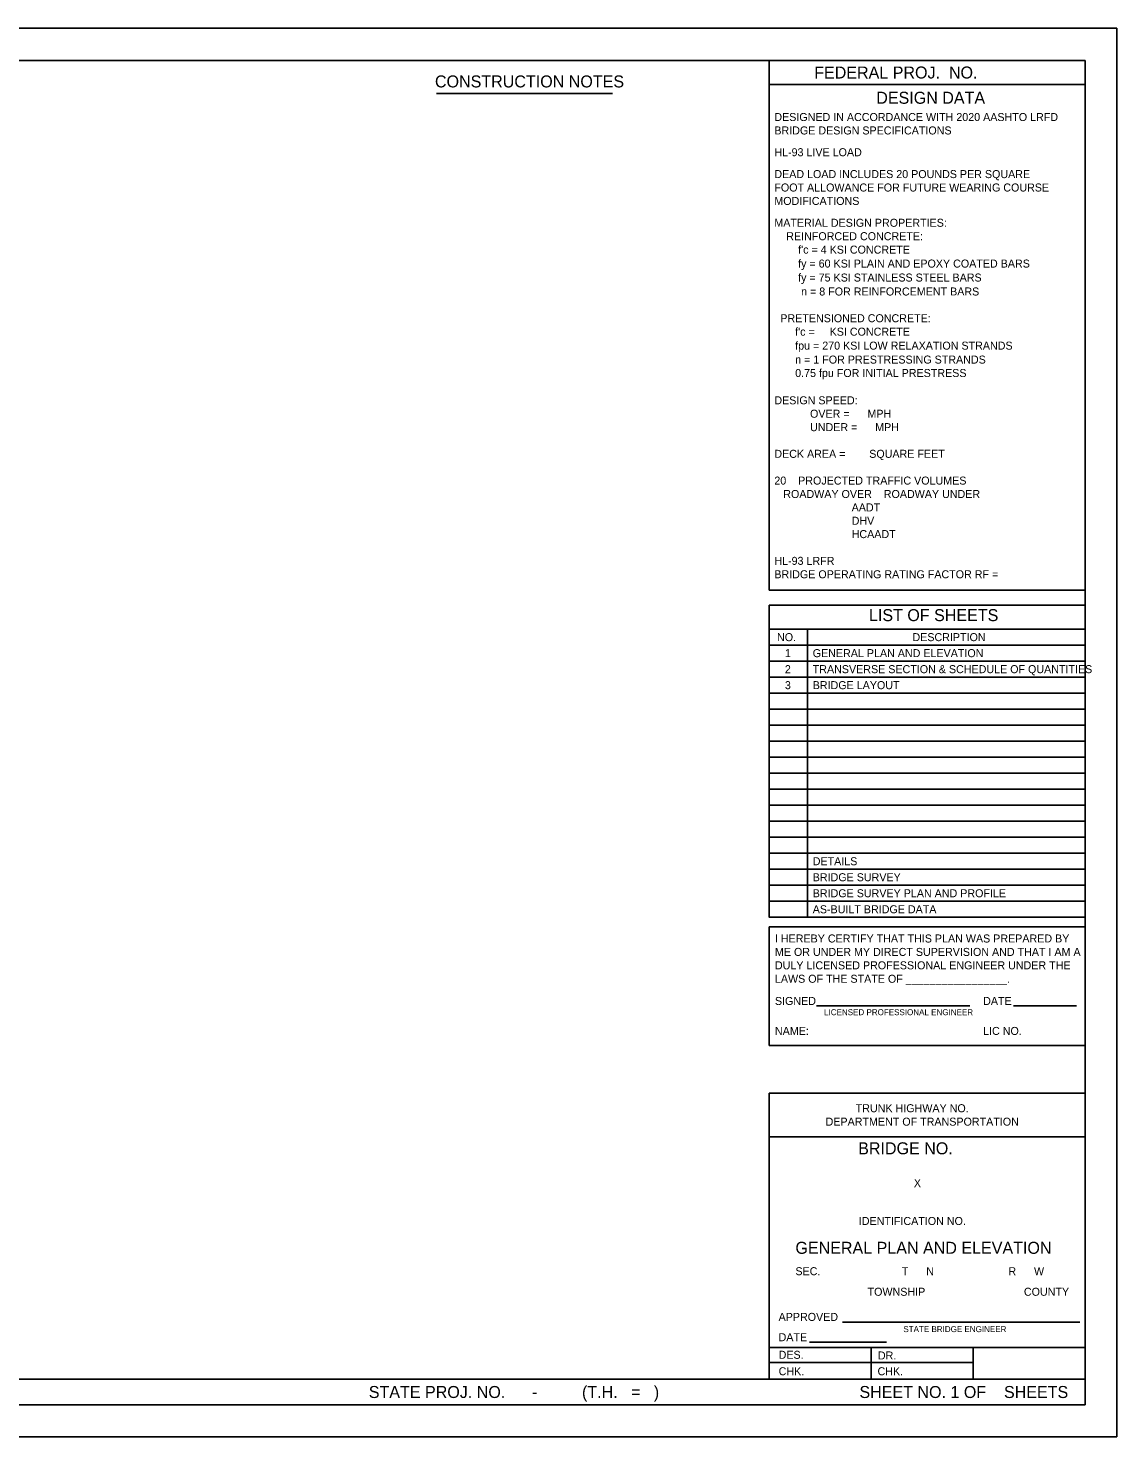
# Model space of a CAD drawing. Extents: x 0 to 1.42, y 0 to 0.92.
# Drawn here: x 0.708 to 1.417, y 0 to 0.917 of the extents above; entities that cross this region are included whole.
import ezdxf

# ---------------------------------------------------------------- set-up
doc = ezdxf.new("R2010")
doc.units = 0
for name, color, linetype in [('Border', 7, 'Continuous'), ('BR', 7, 'Continuous'), ('PLOT AIDS', 7, 'Continuous'), ('SHT1', 7, 'Continuous'), ('STD', 7, 'Continuous'), ('Txt', 7, 'Continuous')]:
    doc.layers.add(name, color=color, linetype=linetype)

msp = doc.modelspace()

# ---------------------------------------------------------------- linework, layer by layer
at = {"layer": 'Border'}
msp.add_lwpolyline([(0.0625, 0.89564), (1.39604, 0.89564), (1.39604, 0.02083), (0.0625, 0.02083)], close=True, dxfattribs=at)
at = {"layer": 'BR'}
for p, q in [((1.19052, 0.5256), (1.39604, 0.5256)), ((1.39604, 0.22365), (1.19052, 0.22365)), ((1.19052, 0.22365), (1.19052, 0.0375)), ((1.39604, 0.19526), (1.19052, 0.19526)), ((1.19052, 0.05819), (1.3961, 0.05819)), ((1.25687, 0.05819), (1.25687, 0.0375)), ((1.32317, 0.05819), (1.32317, 0.0375))]:
    msp.add_line(p, q, dxfattribs=at)
at = {"layer": 'PLOT AIDS'}
msp.add_lwpolyline([(0, 0.91668), (1.4167, 0.91668), (1.4167, 0), (0, 0)], close=True, dxfattribs=at)
at = {"layer": 'SHT1'}
for p, q in [((1.21536, 0.5256), (1.21536, 0.3381)), ((1.19052, 0.51518), (1.39604, 0.51518)), ((1.19052, 0.50477), (1.39604, 0.50477)), ((1.19052, 0.49435), (1.39604, 0.49435)), ((1.19052, 0.48393), (1.39604, 0.48393)), ((1.19052, 0.47352), (1.39604, 0.47352)), ((1.19052, 0.4631), (1.39604, 0.4631)), ((1.19052, 0.45268), (1.39604, 0.45268)), ((1.19052, 0.44227), (1.39604, 0.44227)), ((1.19052, 0.43185), (1.39604, 0.43185)), ((1.19052, 0.42143), (1.39604, 0.42143)), ((1.19052, 0.41102), (1.39604, 0.41102)), ((1.19052, 0.4006), (1.39604, 0.4006)), ((1.19052, 0.39018), (1.39604, 0.39018)), ((1.19052, 0.37977), (1.39604, 0.37977)), ((1.19052, 0.36935), (1.39604, 0.36935)), ((1.19052, 0.35893), (1.39604, 0.35893)), ((1.19052, 0.34852), (1.39604, 0.34852)), ((1.19052, 0.25468), (1.19052, 0.33187)), ((1.19052, 0.33187), (1.39604, 0.33187)), ((1.39604, 0.25468), (1.19052, 0.25468)), ((1.23821, 0.07469), (1.39258, 0.07469)), ((1.19052, 0.04838), (1.32317, 0.04838)), ((0.06258, 0.0375), (1.39596, 0.0375))]:
    msp.add_line(p, q, dxfattribs=at)
at = {"layer": 'STD'}
msp.add_lwpolyline([(1.19052, 0.5412), (1.39604, 0.5412), (1.39604, 0.3381), (1.19052, 0.3381)], close=True, dxfattribs=at)
at = {"layer": 'Txt'}
for p, q in [((1.19052, 0.89564), (1.19052, 0.55091)), ((1.19052, 0.88001), (1.39604, 0.88001)), ((0.97399, 0.87406), (1.08862, 0.87406)), ((1.19052, 0.55091), (1.39604, 0.55091)), ((1.2213, 0.28051), (1.32115, 0.28051)), ((1.34948, 0.28051), (1.39046, 0.28051)), ((1.21667, 0.06155), (1.26683, 0.06155))]:
    msp.add_line(p, q, dxfattribs=at)

# ---------------------------------------------------------------- texts
for s, height, p in [('FEDERAL PROJ.  NO.                 ', 0.0078125, (1.21979, 0.88392)), ('CONSTRUCTION NOTES', 0.0078125, (0.97304, 0.87811)), ('DESIGN DATA', 0.0078125, (1.26017, 0.86749)), ('DESIGNED IN ACCORDANCE WITH 2020 AASHTO LRFD', 0.0052083, (1.19386, 0.85625)), ('BRIDGE DESIGN SPECIFICATIONS', 0.0052083, (1.19386, 0.84752)), ('HL-93 LIVE LOAD', 0.0052083, (1.19386, 0.83334)), ('DEAD LOAD INCLUDES 20 POUNDS PER SQUARE', 0.0052083, (1.19386, 0.81912)), ('FOOT ALLOWANCE FOR FUTURE WEARING COURSE', 0.0052083, (1.19386, 0.81039)), ('MODIFICATIONS', 0.0052083, (1.19386, 0.80165)), ('MATERIAL DESIGN PROPERTIES:', 0.0052083, (1.19386, 0.78744)), ('    REINFORCED CONCRETE:', 0.0052083, (1.19386, 0.7787)), ("        f'c = 4 KSI CONCRETE", 0.0052083, (1.19386, 0.76997)), ('        fy = 60 KSI PLAIN AND EPOXY COATED BARS', 0.0052083, (1.19386, 0.76089)), ('        fy = 75 KSI STAINLESS STEEL BARS', 0.0052083, (1.19386, 0.7518)), ('         n = 8 FOR REINFORCEMENT BARS', 0.0052083, (1.19386, 0.74272)), ('  PRETENSIONED CONCRETE:', 0.0052083, (1.19386, 0.72531)), ("       f'c =     KSI CONCRETE", 0.0052083, (1.19386, 0.71657)), ('       fpu = 270 KSI LOW RELAXATION STRANDS', 0.0052083, (1.19386, 0.70749)), ('       n = 1 FOR PRESTRESSING STRANDS', 0.0052083, (1.19386, 0.69841)), ('       0.75 fpu FOR INITIAL PRESTRESS', 0.0052083, (1.19386, 0.68968)), ('DESIGN SPEED:', 0.0052083, (1.19386, 0.67191)), ('            OVER =      MPH', 0.0052083, (1.19386, 0.66318)), ('            UNDER =      MPH', 0.0052083, (1.19386, 0.65444)), ('DECK AREA =        SQUARE FEET', 0.0052083, (1.19386, 0.63708)), ('20    PROJECTED TRAFFIC VOLUMES', 0.0052083, (1.19386, 0.61967)), ('   ROADWAY OVER    ROADWAY UNDER', 0.0052083, (1.19386, 0.61093)), ('                          AADT         ', 0.0052083, (1.19386, 0.6022)), ('                          DHV          ', 0.0052083, (1.19386, 0.59352)), ('                          HCAADT       ', 0.0052083, (1.19386, 0.58484)), ('HL-93 LRFR', 0.005208, (1.19386, 0.56744)), ('BRIDGE OPERATING RATING FACTOR RF =    ', 0.0052083, (1.19386, 0.5587)), ('LIST OF SHEETS', 0.0078125, (1.25543, 0.53081)), ('NO.', 0.005208, (1.19562, 0.51779)), ('DESCRIPTION', 0.0052083, (1.28372, 0.51779)), ('1', 0.00521, (1.20071, 0.50737)), ('GENERAL PLAN AND ELEVATION', 0.0052083, (1.21883, 0.50737)), ('2', 0.00521, (1.20072, 0.49695)), ('TRANSVERSE SECTION & SCHEDULE OF QUANTITIES', 0.0052083, (1.21883, 0.49695)), ('3', 0.00521, (1.20074, 0.48654)), ('BRIDGE LAYOUT', 0.0052083, (1.21883, 0.48654)), ('DETAILS ', 0.005208, (1.21883, 0.37195)), ('BRIDGE SURVEY', 0.0052083, (1.21883, 0.36154)), ('BRIDGE SURVEY PLAN AND PROFILE', 0.0052083, (1.21883, 0.35112)), ('AS-BUILT BRIDGE DATA', 0.0052083, (1.21883, 0.3407)), ('I HEREBY CERTIFY THAT THIS PLAN WAS PREPARED BY', 0.0052083, (1.19424, 0.32169)), ('ME OR UNDER MY DIRECT SUPERVISION AND THAT I AM A', 0.0052083, (1.19424, 0.31295)), ('DULY LICENSED PROFESSIONAL ENGINEER UNDER THE', 0.0052083, (1.19424, 0.30422)), ('LAWS OF THE STATE OF _________________.', 0.0052083, (1.19424, 0.29548)), ('SIGNED', 0.005208, (1.19424, 0.28104)), ('DATE', 0.005208, (1.32971, 0.28104)), ('LICENSED PROFESSIONAL ENGINEER', 0.0039062, (1.22622, 0.27438)), ('NAME:                                         ', 0.0052083, (1.19424, 0.26153)), ('LIC NO.        ', 0.0052083, (1.32971, 0.26153)), ('TRUNK HIGHWAY NO.    ', 0.0052083, (1.2468, 0.21122)), ('DEPARTMENT OF TRANSPORTATION', 0.0052083, (1.2272, 0.20249)), ('BRIDGE NO.      ', 0.0078125, (1.24842, 0.18384)), ('X', 0.00521, (1.28464, 0.16246)), ('IDENTIFICATION NO.    ', 0.0052083, (1.24883, 0.13786)), ('GENERAL PLAN AND ELEVATION', 0.0078125, (1.20757, 0.11909)), ('SEC.      ', 0.005208, (1.20757, 0.10516)), ('T      N', 0.005208, (1.27681, 0.10516)), ('R      W', 0.005208, (1.34617, 0.10516)), ('           TOWNSHIP', 0.0052083, (1.23323, 0.0918)), ('           COUNTY', 0.0052083, (1.33495, 0.0918)), ('APPROVED', 0.005208, (1.19662, 0.07544)), ('DATE', 0.005208, (1.19662, 0.06222)), ('STATE BRIDGE ENGINEER', 0.0039062, (1.2778, 0.06814)), ('DES.               ', 0.0052083, (1.19666, 0.05078)), ('DR.                ', 0.0052083, (1.26123, 0.05033)), ('CHK.               ', 0.0052083, (1.19666, 0.04006)), ('CHK.              ', 0.0052083, (1.26101, 0.04006)), ('STATE PROJ. NO.      -          (T.H.   =   )', 0.0078125, (0.92998, 0.02526)), ('SHEET NO. 1 OF    SHEETS', 0.0078125, (1.24924, 0.02526))]:
    msp.add_text(s, height=height, dxfattribs=at).set_placement(p)

doc.saveas('drawing.dxf')
